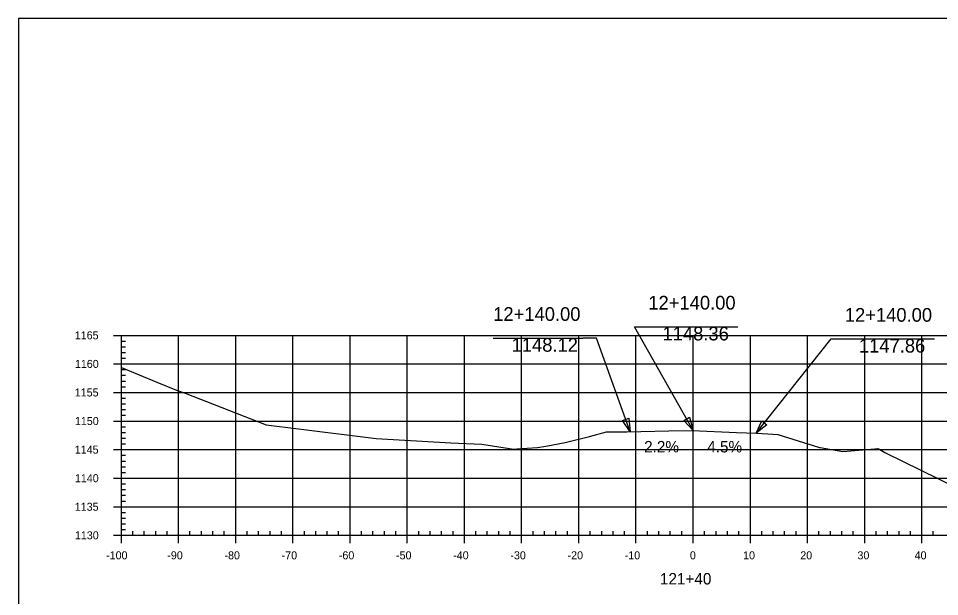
# Model space of a CAD drawing. Extents: x 688474 to 694748, y 765018 to 767373.
# Drawn here: x 690038.3 to 690199.4, y 765122.1 to 765223.3 of the extents above; entities that cross this region are included whole.
import ezdxf

# ---------------------------------------------------------------- set-up
doc = ezdxf.new("R2010")
doc.units = 0
for name, color, linetype in [('60', 7, 'Continuous'), ('Default', 7, 'Continuous'), ('R_Exist Surface', 7, 'Continuous'), ('R_Grid', 7, 'Continuous'), ('R_No Plot', 7, 'Continuous'), ('R_Xsect Slope', 7, 'Continuous')]:
    doc.layers.add(name, color=color, linetype=linetype)

msp = doc.modelspace()

# ---------------------------------------------------------------- linework, layer by layer
at = {"layer": '60'}
for p, q in [((690054.91, 765167.86), (690057.71, 765167.86)), ((690056.31, 765132.86), (690056.31, 765167.86)), ((690056.31, 765166.86), (690057.01, 765166.86)), ((690056.31, 765165.86), (690057.01, 765165.86)), ((690056.31, 765164.86), (690057.01, 765164.86)), ((690056.31, 765163.86), (690057.01, 765163.86)), ((690054.91, 765162.86), (690057.71, 765162.86)), ((690056.31, 765161.86), (690057.01, 765161.86)), ((690056.31, 765160.86), (690057.01, 765160.86)), ((690056.31, 765159.86), (690057.01, 765159.86)), ((690056.31, 765158.86), (690057.01, 765158.86)), ((690054.91, 765157.86), (690057.71, 765157.86)), ((690056.31, 765156.86), (690057.01, 765156.86)), ((690056.31, 765155.86), (690057.01, 765155.86)), ((690056.31, 765154.86), (690057.01, 765154.86)), ((690054.91, 765152.86), (690057.71, 765152.86)), ((690056.31, 765153.86), (690057.01, 765153.86)), ((690056.31, 765151.86), (690057.01, 765151.86)), ((690056.31, 765150.86), (690057.01, 765150.86)), ((690056.31, 765149.86), (690057.01, 765149.86)), ((690054.91, 765147.86), (690057.71, 765147.86)), ((690056.31, 765148.86), (690057.01, 765148.86)), ((690056.31, 765146.86), (690057.01, 765146.86)), ((690056.31, 765145.86), (690057.01, 765145.86)), ((690056.31, 765144.86), (690057.01, 765144.86)), ((690054.91, 765142.86), (690057.71, 765142.86)), ((690056.31, 765143.86), (690057.01, 765143.86)), ((690056.31, 765141.86), (690057.01, 765141.86)), ((690056.31, 765140.86), (690057.01, 765140.86)), ((690056.31, 765139.86), (690057.01, 765139.86)), ((690054.91, 765137.86), (690057.71, 765137.86)), ((690056.31, 765138.86), (690057.01, 765138.86)), ((690056.31, 765136.86), (690057.01, 765136.86)), ((690056.31, 765135.86), (690057.01, 765135.86)), ((690056.31, 765134.86), (690057.01, 765134.86)), ((690056.31, 765131.46), (690056.31, 765134.26)), ((690056.31, 765133.86), (690057.01, 765133.86)), ((690058.31, 765132.86), (690058.31, 765133.56)), ((690060.31, 765132.86), (690060.31, 765133.56)), ((690062.31, 765132.86), (690062.31, 765133.56)), ((690064.31, 765132.86), (690064.31, 765133.56)), ((690066.31, 765131.46), (690066.31, 765134.26)), ((690068.31, 765132.86), (690068.31, 765133.56)), ((690070.31, 765132.86), (690070.31, 765133.56)), ((690072.31, 765132.86), (690072.31, 765133.56)), ((690074.31, 765132.86), (690074.31, 765133.56)), ((690076.31, 765131.46), (690076.31, 765134.26)), ((690078.31, 765132.86), (690078.31, 765133.56)), ((690080.31, 765132.86), (690080.31, 765133.56)), ((690082.31, 765132.86), (690082.31, 765133.56)), ((690084.31, 765132.86), (690084.31, 765133.56)), ((690086.31, 765131.46), (690086.31, 765134.26)), ((690088.31, 765132.86), (690088.31, 765133.56)), ((690090.31, 765132.86), (690090.31, 765133.56)), ((690092.31, 765132.86), (690092.31, 765133.56)), ((690094.31, 765132.86), (690094.31, 765133.56)), ((690096.31, 765131.46), (690096.31, 765134.26)), ((690098.31, 765132.86), (690098.31, 765133.56)), ((690100.31, 765132.86), (690100.31, 765133.56)), ((690102.31, 765132.86), (690102.31, 765133.56)), ((690104.31, 765132.86), (690104.31, 765133.56)), ((690106.31, 765131.46), (690106.31, 765134.26)), ((690108.31, 765132.86), (690108.31, 765133.56)), ((690110.31, 765132.86), (690110.31, 765133.56)), ((690112.31, 765132.86), (690112.31, 765133.56)), ((690114.31, 765132.86), (690114.31, 765133.56)), ((690116.31, 765131.46), (690116.31, 765134.26)), ((690118.31, 765132.86), (690118.31, 765133.56)), ((690120.31, 765132.86), (690120.31, 765133.56)), ((690122.31, 765132.86), (690122.31, 765133.56)), ((690124.31, 765132.86), (690124.31, 765133.56)), ((690126.31, 765131.46), (690126.31, 765134.26)), ((690128.31, 765132.86), (690128.31, 765133.56)), ((690130.31, 765132.86), (690130.31, 765133.56)), ((690132.31, 765132.86), (690132.31, 765133.56)), ((690134.31, 765132.86), (690134.31, 765133.56)), ((690136.31, 765131.46), (690136.31, 765134.26)), ((690138.31, 765132.86), (690138.31, 765133.56)), ((690140.31, 765132.86), (690140.31, 765133.56)), ((690142.31, 765132.86), (690142.31, 765133.56)), ((690144.31, 765132.86), (690144.31, 765133.56)), ((690146.31, 765131.46), (690146.31, 765134.26)), ((690148.31, 765132.86), (690148.31, 765133.56)), ((690150.31, 765132.86), (690150.31, 765133.56)), ((690152.31, 765132.86), (690152.31, 765133.56)), ((690154.31, 765132.86), (690154.31, 765133.56)), ((690156.31, 765131.46), (690156.31, 765134.26)), ((690158.31, 765132.86), (690158.31, 765133.56)), ((690160.31, 765132.86), (690160.31, 765133.56)), ((690162.31, 765132.86), (690162.31, 765133.56)), ((690164.31, 765132.86), (690164.31, 765133.56)), ((690166.31, 765131.46), (690166.31, 765134.26)), ((690168.31, 765132.86), (690168.31, 765133.56)), ((690170.31, 765132.86), (690170.31, 765133.56)), ((690172.31, 765132.86), (690172.31, 765133.56)), ((690174.31, 765132.86), (690174.31, 765133.56)), ((690176.31, 765131.46), (690176.31, 765134.26)), ((690178.31, 765132.86), (690178.31, 765133.56)), ((690180.31, 765132.86), (690180.31, 765133.56)), ((690182.31, 765132.86), (690182.31, 765133.56)), ((690184.31, 765132.86), (690184.31, 765133.56)), ((690186.31, 765131.46), (690186.31, 765134.26)), ((690188.31, 765132.86), (690188.31, 765133.56)), ((690190.31, 765132.86), (690190.31, 765133.56)), ((690192.31, 765132.86), (690192.31, 765133.56)), ((690194.31, 765132.86), (690194.31, 765133.56)), ((690196.31, 765131.46), (690196.31, 765134.26)), ((690198.31, 765132.86), (690198.31, 765133.56)), ((690054.91, 765132.86), (690057.71, 765132.86)), ((690056.31, 765132.86), (690256.31, 765132.86))]:
    msp.add_line(p, q, dxfattribs=at)
at = {"layer": 'R_Exist Surface'}
for p, q in [((690148.47, 765169.37), (690164.14, 765169.37)), ((690121.34, 765167.39), (690137.02, 765167.39)), ((690182.83, 765167.24), (690198.5, 765167.24))]:
    msp.add_line(p, q, dxfattribs=at)
for points in [[(690156.31, 765151.22), (690146.07, 765169.37), (690148.47, 765169.37)], [(690145.31, 765150.99), (690139.42, 765167.39), (690137.02, 765167.39)], [(690167.31, 765150.72), (690180.43, 765167.24), (690182.83, 765167.24)], [(690056.31, 765162.22), (690062.49, 765159.65), (690065.96, 765158.26), (690067.44, 765157.73), (690081.63, 765152.22), (690087.3, 765151.49), (690100.85, 765149.8), (690113.94, 765149.06), (690119.37, 765148.79), (690124.19, 765148.05), (690124.87, 765147.95), (690125.48, 765147.99), (690129.1, 765148.22), (690130.53, 765148.47), (690133.95, 765149.08), (690138.17, 765150.18), (690141.13, 765150.95), (690142.39, 765150.97), (690144.72, 765150.97), (690152.08, 765151.15), (690156.16, 765151.22), (690163.91, 765150.88), (690167.4, 765150.72), (690169.37, 765150.61), (690171.14, 765150.5), (690178.22, 765148.29), (690178.41, 765148.23), (690178.51, 765148.21), (690182.49, 765147.52), (690188.1, 765147.97), (690188.47, 765148), (690188.66, 765148.04), (690189.8, 765147.38), (690202.31, 765141.25)]]:
    msp.add_lwpolyline(points, dxfattribs=at)
for points in [[(690145.31, 765150.99), (690143.97, 765152.98), (690145.07, 765153.38)], [(690156.31, 765151.22), (690154.65, 765152.96), (690155.67, 765153.54)], [(690167.31, 765150.72), (690168.3, 765152.91), (690169.21, 765152.18)]]:
    msp.add_lwpolyline(points, close=True, dxfattribs=at)
at = {"layer": 'R_Grid'}
for p, q in [((690056.31, 765167.86), (690256.31, 765167.86)), ((690056.31, 765132.86), (690056.31, 765167.86)), ((690066.31, 765132.86), (690066.31, 765167.86)), ((690076.31, 765132.86), (690076.31, 765167.86)), ((690086.31, 765132.86), (690086.31, 765167.86)), ((690096.31, 765132.86), (690096.31, 765167.86)), ((690106.31, 765132.86), (690106.31, 765167.86)), ((690116.31, 765132.86), (690116.31, 765167.86)), ((690126.31, 765132.86), (690126.31, 765167.86)), ((690136.31, 765132.86), (690136.31, 765167.86)), ((690146.31, 765132.86), (690146.31, 765167.86)), ((690156.31, 765132.86), (690156.31, 765167.86)), ((690166.31, 765132.86), (690166.31, 765167.86)), ((690176.31, 765132.86), (690176.31, 765167.86)), ((690186.31, 765132.86), (690186.31, 765167.86)), ((690196.31, 765132.86), (690196.31, 765167.86)), ((690056.31, 765162.86), (690256.31, 765162.86)), ((690056.31, 765157.86), (690256.31, 765157.86)), ((690056.31, 765152.86), (690256.31, 765152.86)), ((690056.31, 765147.86), (690256.31, 765147.86)), ((690056.31, 765142.86), (690256.31, 765142.86)), ((690056.31, 765137.86), (690256.31, 765137.86)), ((690056.31, 765132.86), (690256.31, 765132.86))]:
    msp.add_line(p, q, dxfattribs=at)
at = {"layer": 'R_No Plot'}
msp.add_lwpolyline([(690038.31, 765017.86), (690354.49, 765017.86), (690354.49, 765223.32), (690038.31, 765223.32)], close=True, dxfattribs=at)

# ---------------------------------------------------------------- texts
at = {"layer": '60'}
for s, height, p in [('1165', 1.4, (690048.16, 765167.16)), ('1160', 1.4, (690048.18, 765162.16)), ('1155', 1.4, (690048.16, 765157.16)), ('1150', 1.4, (690048.18, 765152.16)), ('1145', 1.4, (690048.16, 765147.16)), ('1140', 1.4, (690048.18, 765142.16)), ('1135', 1.4, (690048.16, 765137.16)), ('1130', 1.4, (690048.18, 765132.16)), ('-100', 1.4, (690053.64, 765128.66)), ('-90', 1.4, (690064.34, 765128.66)), ('-80', 1.4, (690074.34, 765128.66)), ('-70', 1.4, (690084.34, 765128.66)), ('-60', 1.4, (690094.34, 765128.66)), ('-50', 1.4, (690104.34, 765128.66)), ('-40', 1.4, (690114.34, 765128.66)), ('-30', 1.4, (690124.34, 765128.66)), ('-20', 1.4, (690134.34, 765128.66)), ('-10', 1.4, (690144.34, 765128.66)), ('0', 1.4, (690155.74, 765128.66)), ('10', 1.4, (690165.04, 765128.66)), ('20', 1.4, (690175.04, 765128.66)), ('30', 1.4, (690185.04, 765128.66)), ('40', 1.4, (690195.04, 765128.66)), ('121+40', 2, (690150.5, 765124.26))]:
    msp.add_text(s, height=height, dxfattribs=at).set_placement(p)
at = {"layer": 'Default'}
for s, p in [('2.2%', (690147.73, 765147.37)), ('4.5%', (690158.77, 765147.37))]:
    msp.add_text(s, height=2, dxfattribs=at).set_placement(p)
at = {"layer": 'R_Xsect Slope'}
for s, p in [('12+140.00', (690148.47, 765172.37)), ('12+140.00', (690121.34, 765170.39)), ('12+140.00', (690182.83, 765170.24)), ('1148.36', (690150.95, 765166.97)), ('1148.12', (690124.56, 765164.99)), ('1147.86', (690185.3, 765164.84))]:
    msp.add_text(s, height=2.4, dxfattribs=at).set_placement(p)

doc.saveas('drawing.dxf')
